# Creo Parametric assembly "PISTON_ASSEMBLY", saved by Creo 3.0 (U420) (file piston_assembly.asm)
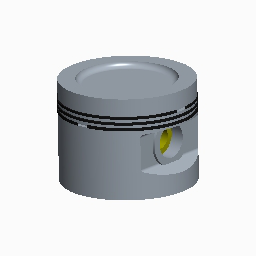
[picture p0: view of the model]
Units: millimeter Kilogram Sec (mmKs); MM, KILOGRAM, SECS

Created from: INLBS_ASM_DESIGN.ASM

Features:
  1. datum plane "ASM_RIGHT"
  2. datum plane "ASM_TOP"
  3. datum plane "ASM_FRONT"
  4. coordinate system
  5. component "PISTON"
  6. component "PISTON_PIN", "PISTON_PIN2.PRT"
  7. component "RING_TOP"
  8. component "RING_BOTTOM"
  9. datum plane "ADTM1"
  10. component "RING_OIL"
  11. datum axis "PISTON"

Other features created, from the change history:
  component "RING_BOTTOM.PRT" (2 times)
  component "RING_OIL.PRT"
  component "PISTON.PRT"
  component "PISTON_PIN.PRT"
  component "RING_TOP.PRT"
